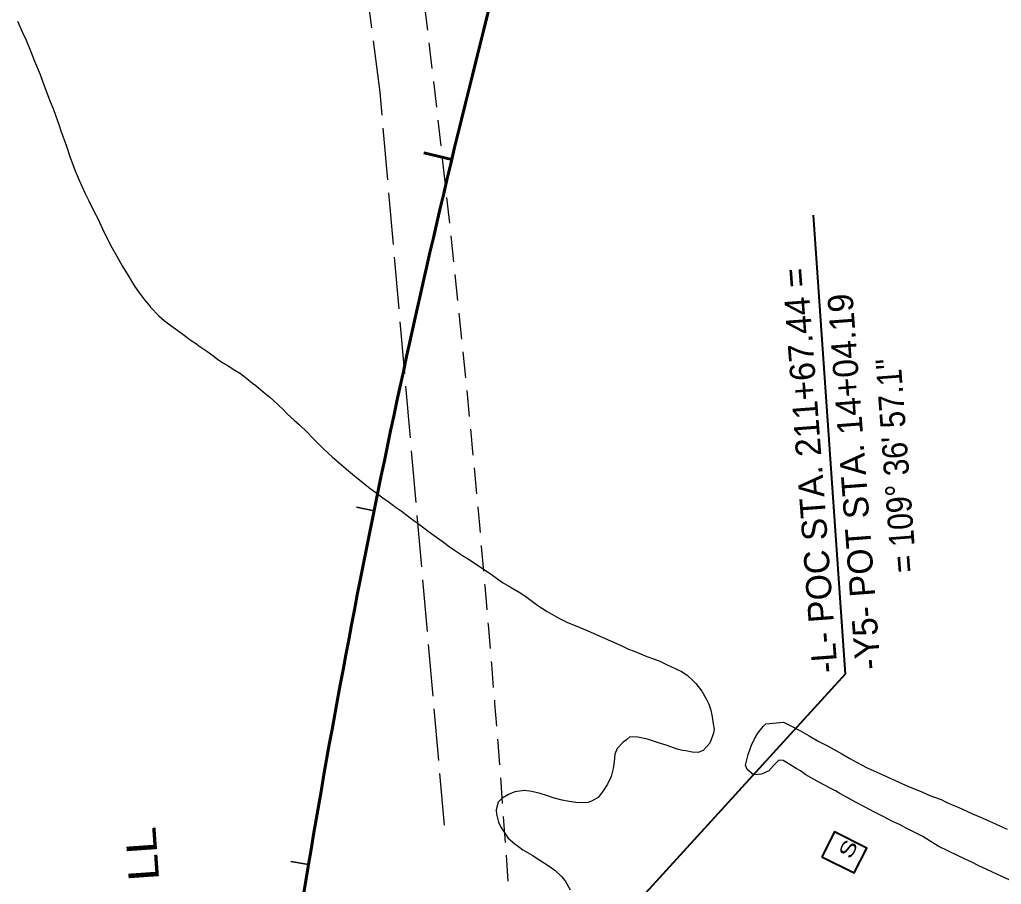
# Model space of a CAD drawing. Extents: x 2399800 to 2400616, y 567351 to 568869.
# Drawn here: x 2400111.3 to 2400384.1, y 568508.2 to 568748.5 of the extents above; entities that cross this region are included whole.
import ezdxf
from ezdxf.enums import TextEntityAlignment as Align

# ---------------------------------------------------------------- set-up
doc = ezdxf.new("R2010")
doc.units = 0
doc.header["$LTSCALE"] = 2.4
doc.linetypes.add('LONG_DASHED', pattern=[7.5, 6, -1.5])
doc.linetypes.add('MEDIUM_DASHED', pattern=[4.5, 3, -1.5])
for name, color, linetype, lineweight in [('11', 7, 'Continuous', 25), ('17', 7, 'MEDIUM_DASHED', 25), ('19', 7, 'LONG_DASHED', 25), ('27', 7, 'Continuous', 80), ('3', 7, 'MEDIUM_DASHED', 35), ('38', 7, 'Continuous', 13), ('4', 7, 'Continuous', 35), ('61', 7, 'Continuous', 40), ('62', 7, 'Continuous', 60), ('8', 7, 'Continuous', 40)]:
    doc.layers.add(name, color=color, linetype=linetype, lineweight=lineweight)
doc.layers.add('28', color=7, linetype='Continuous')

msp = doc.modelspace()

# ---------------------------------------------------------------- linework, layer by layer
at = {"layer": '11'}
for points in [[(2400110.722, 568748.027), (2400112.146, 568744.947), (2400113.078, 568742.769), (2400114.538, 568739.38), (2400115.441, 568736.978), (2400117.001, 568733.194), (2400118.005, 568730.398), (2400119.59, 568726.231), (2400120.754, 568723.49), (2400122.31, 568719.099), (2400122.797, 568717.588), (2400124.299, 568713.356), (2400125.293, 568710.485), (2400126.749, 568706.488), (2400127.857, 568703.906), (2400129.446, 568700.348), (2400130.529, 568698.15), (2400132.027, 568695.061), (2400132.999, 568693.182), (2400134.303, 568690.346), (2400135.209, 568688.552), (2400136.968, 568685.124)], [(2400136.968, 568685.124), (2400138.33, 568682.738), (2400139.813, 568680.107), (2400141.435, 568677.382), (2400143.178, 568674.413), (2400144.859, 568672.137), (2400146.03, 568670.613), (2400147.08, 568669.333), (2400147.666, 568668.571), (2400149.946, 568666.217), (2400151.445, 568664.878), (2400152.695, 568663.953), (2400155.268, 568662.093), (2400157.002, 568660.8), (2400158.736, 568659.507), (2400160.414, 568658.373), (2400161.104, 568657.826), (2400163.342, 568656.314), (2400165.011, 568655.106), (2400166.325, 568654.096), (2400167.724, 568653.152), (2400169.283, 568652.262), (2400171.111, 568651.109), (2400172.66, 568650.144), (2400174.459, 568648.767), (2400175.968, 568647.503), (2400176.938, 568646.767), (2400178.997, 568645.05), (2400180.786, 568643.598), (2400183.03, 568641.552), (2400184.585, 568640.054), (2400185.655, 568638.924), (2400187.63, 568637.143), (2400189.064, 568635.889), (2400191.299, 568633.769), (2400192.704, 568632.29), (2400195.729, 568629.229), (2400198.243, 568626.92), (2400200.088, 568625.308), (2400202.697, 568623.139), (2400204.336, 568621.706), (2400206.75, 568619.79), (2400208.269, 568618.601), (2400210.618, 568616.771), (2400212.212, 568615.572), (2400213.676, 568614.543), (2400215.894, 568612.882), (2400217.294, 568611.937), (2400219.372, 568610.37), (2400220.826, 568609.266), (2400222.43, 568608.142), (2400224.854, 568606.302), (2400226.523, 568605.093), (2400229.096, 568603.233), (2400230.69, 568602.035), (2400232.154, 568601.005), (2400234.402, 568599.569), (2400235.961, 568598.679), (2400239.103, 568596.516), (2400242.321, 568594.343), (2400244.195, 568592.956), (2400245.528, 568592.096), (2400247.851, 568590.649), (2400250.119, 568589.362), (2400251.938, 568588.134), (2400255.34, 568585.632), (2400257.868, 568584.007), (2400261.125, 568582.133), (2400263.347, 568581.081), (2400266.813, 568579.637), (2400268.98, 568578.744), (2400271.716, 568577.547), (2400273.154, 568576.902), (2400275.526, 568575.83), (2400278.478, 568574.53), (2400280.485, 568573.581), (2400282.083, 568572.991), (2400285.623, 568571.537), (2400287.725, 568570.729), (2400289.173, 568570.159), (2400291.041, 568569.305), (2400293.478, 568568.148), (2400295.195, 568567.314), (2400296.819, 568566.34), (2400298.513, 568564.747), (2400299.174, 568563.975), (2400300.875, 568561.849), (2400302.127, 568559.781), (2400302.838, 568558.242), (2400303.381, 568556.571), (2400303.744, 568554.697), (2400304.033, 568552.831), (2400304.286, 568551.276), (2400304.148, 568550.228), (2400303.092, 568547.397), (2400301.226, 568545.357), (2400299.865, 568544.851), (2400298.199, 568544.917), (2400296.422, 568545.302), (2400295.524, 568545.419), (2400294.046, 568545.765)], [(2400337.977, 568534.145), (2400336.698, 568534.846), (2400334.775, 568535.859), (2400332.927, 568536.863), (2400331.294, 568537.762), (2400329.811, 568538.642), (2400328.272, 568539.681), (2400327.068, 568540.372), (2400325.305, 568541.44), (2400323.476, 568542.593), (2400322.269, 568542.676), (2400320.875, 568541.336), (2400319.452, 568539.771), (2400317.498, 568538.809), (2400315.194, 568538.654), (2400313.479, 568540.097), (2400313.028, 568541.298), (2400313.72, 568544.253), (2400314.672, 568546.869), (2400315.516, 568548.662), (2400316.48, 568550.211), (2400317.942, 568552.074), (2400318.64, 568552.745), (2400323.577, 568553.24)], [(2400323.577, 568553.24), (2400325.08, 568552.51), (2400328.067, 568550.9), (2400330.699, 568549.489), (2400333.246, 568548.013), (2400335.953, 568546.593), (2400339.78, 568544.416), (2400341.973, 568543.139), (2400345.024, 568541.444), (2400346.808, 568540.525), (2400349.544, 568539.329), (2400351.197, 568538.58), (2400354.567, 568536.996), (2400356.66, 568536.113), (2400358.098, 568535.468), (2400360.34, 568534.564), (2400361.788, 568533.994), (2400363.366, 568533.255), (2400364.954, 568532.59), (2400367.355, 568531.742), (2400368.783, 568531.022), (2400370.95, 568530.128), (2400372.314, 568529.493), (2400374.546, 568528.515), (2400376.049, 568527.785), (2400378.291, 568526.883), (2400380.019, 568526.123), (2400382.465, 568525.041), (2400384.044, 568524.301), (2400385.697, 568523.552)], [(2400294.046, 568545.765), (2400291.206, 568546.747), (2400288.58, 568547.624), (2400285.804, 568548.52), (2400283.064, 568549.108), (2400280.864, 568549.168), (2400279.923, 568548.378), (2400279.001, 568547.737), (2400277.324, 568545.977), (2400276.734, 568544.38), (2400276.534, 568542.274), (2400276.214, 568540.412), (2400275.686, 568538.122), (2400274.652, 568536.049), (2400273.414, 568534.155), (2400272.037, 568532.356), (2400270.223, 568531.3), (2400269.256, 568530.894), (2400267.73, 568530.865), (2400265.839, 568530.961), (2400263.968, 568531.206), (2400262.032, 568531.536), (2400259.61, 568532.234), (2400258.013, 568532.824), (2400255.956, 568533.398), (2400253.6, 568534.012), (2400251.579, 568534.276), (2400248.936, 568533.861), (2400247.172, 568533.179), (2400245.358, 568532.122), (2400244.303, 568531.042), (2400243.719, 568528.911), (2400243.787, 568527.684), (2400244.336, 568525.48), (2400245.067, 568524.09), (2400247.099, 568521.007), (2400248.944, 568519.395), (2400249.923, 568518.733), (2400251.172, 568517.808), (2400253.71, 568516.257), (2400255.613, 568515.094), (2400258.496, 568513.27), (2400260.024, 568512.156), (2400261.849, 568510.394), (2400262.9, 568509.114), (2400264.327, 568506.643)], [(2400386.287, 568509.465), (2400384.055, 568510.443), (2400381.618, 568511.6), (2400379.89, 568512.359), (2400377.882, 568513.307), (2400375.885, 568514.331), (2400373.877, 568515.279), (2400371.72, 568516.247), (2400369.572, 568517.29), (2400366.576, 568518.824), (2400364.318, 568520.187), (2400362.275, 568521.444), (2400360.062, 568522.571), (2400357.85, 568523.699), (2400355.787, 568524.807), (2400353.845, 568525.67), (2400351.277, 568526.997), (2400348.711, 568528.323), (2400346.293, 568529.63), (2400343.726, 568530.956), (2400341.234, 568532.272), (2400339.255, 568533.445), (2400337.977, 568534.145)]]:
    msp.add_lwpolyline(points, dxfattribs=at)
at = {"layer": '17'}
msp.add_arc((2395446.846, 568174.368), 4811.888, 358.84472, 7.18511, dxfattribs=at)
at = {"layer": '19'}
msp.add_lwpolyline([(2400229.34, 568524.653), (2400211.491, 568728.334), (2400192.97, 568869.329)], dxfattribs=at)
at = {"layer": '3', "linetype": 'Continuous', "lineweight": 60}
msp.add_line((2400231.397, 568709.644), (2400223.617, 568711.506), dxfattribs=at)
at = {"layer": '38'}
msp.add_arc((2403051.703, 568034.46), 2900, 165.14066, 170.48811, dxfattribs=at)
at = {"layer": '4'}
for p, q in [((2400209.796, 568612.01), (2400204.896, 568613.005)), ((2400186.645, 568514.515), (2400191.574, 568513.689))]:
    msp.add_line(p, q, dxfattribs=at)
at = {"layer": '61'}
for p, q in [((2400331.812, 568694.105), (2400340.726, 568566.615)), ((2400340.726, 568566.615), (2400172.663, 568382.492))]:
    msp.add_line(p, q, dxfattribs=at)
at = {"layer": '62'}
for start, end in [(165.14066, 170.48811), (170.48821, 180.54867)]:
    msp.add_arc((2403051.703, 568034.46), 2900, start, end, dxfattribs=at)
at = {"layer": '8'}
msp.add_lwpolyline([(2400334.251, 568515.864), (2400343.233, 568511.343), (2400346.701, 568518.235), (2400337.719, 568522.755)], close=True, dxfattribs=at)

# ---------------------------------------------------------------- texts
at = {"layer": '27', "width": 1.2}
msp.add_text('EB2-A LL', height=8.438, rotation=94, dxfattribs=at).set_placement((2400151.055, 568495.473), align=Align.CENTER)
at = {"layer": '28', "width": 1.35}
msp.add_text('S', height=4, rotation=62.433, dxfattribs=at).set_placement((2400343.313, 568517.095), align=Align.CENTER)
at = {"layer": '61'}
for s, p in [('-L- POC STA. 211+67.44 =', (2400338.618, 568567.15)), ('-Y5- POT STA. 14+04.19', (2400350.584, 568568.051))]:
    msp.add_text(s, height=7, rotation=94.303, dxfattribs=at).set_placement(p)
at = {"layer": '61', "width": 0.9}
msp.add_text('= 109° 36\' 57.1"', height=7, rotation=94.303, dxfattribs=at).set_placement((2400356.082, 568654.602), align=Align.RIGHT)

doc.saveas('drawing.dxf')
